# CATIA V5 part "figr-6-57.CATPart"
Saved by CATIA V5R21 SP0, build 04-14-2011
Part number: Part1
Bounding box of the stored display mesh (mm): x -50.648 to 73.742, y -72.183 to 95.277, z -40 to 40
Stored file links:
  D:\CATIA V5R21 E-RESOURCES\CATIA-V5R21\catia-v5r21-prt\c06-catia-v5r21-prt\c06-catia-v5r21-figr-6-57.CATPart
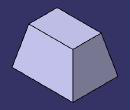
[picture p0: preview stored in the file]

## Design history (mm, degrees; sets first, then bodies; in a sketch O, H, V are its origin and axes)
Body1 (main body)
  Sketch1 on xy-plane, origin (0, 0, 0), H (1, 0, 0), V (0, 1, 0)
    line L1 (-50.6478, 72.1832) -> (50.6478, 72.1832)
    line L2 (50.6478, 72.1832) -> (50.6478, -72.1832)
    line L3 (50.6478, -72.1832) -> (-50.6478, -72.1832)
    line L4 (-50.6478, -72.1832) -> (-50.6478, 72.1832)
    axis line L5 (50.6478, -72.1832) -> (-50.6478, 72.1832)
    horizontal: L1 H, L3 H
    vertical: L2 V, L4 V
    midpoint: O L5
  Pad1: profile Sketch1, direction (0, 0, 1), length 40, mirrored extent
  Draft1: Angle 30, Neutral xy-plane, PullDir (0, 0, 1), SupportToDraft (face of Pad1; face of Pad1)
